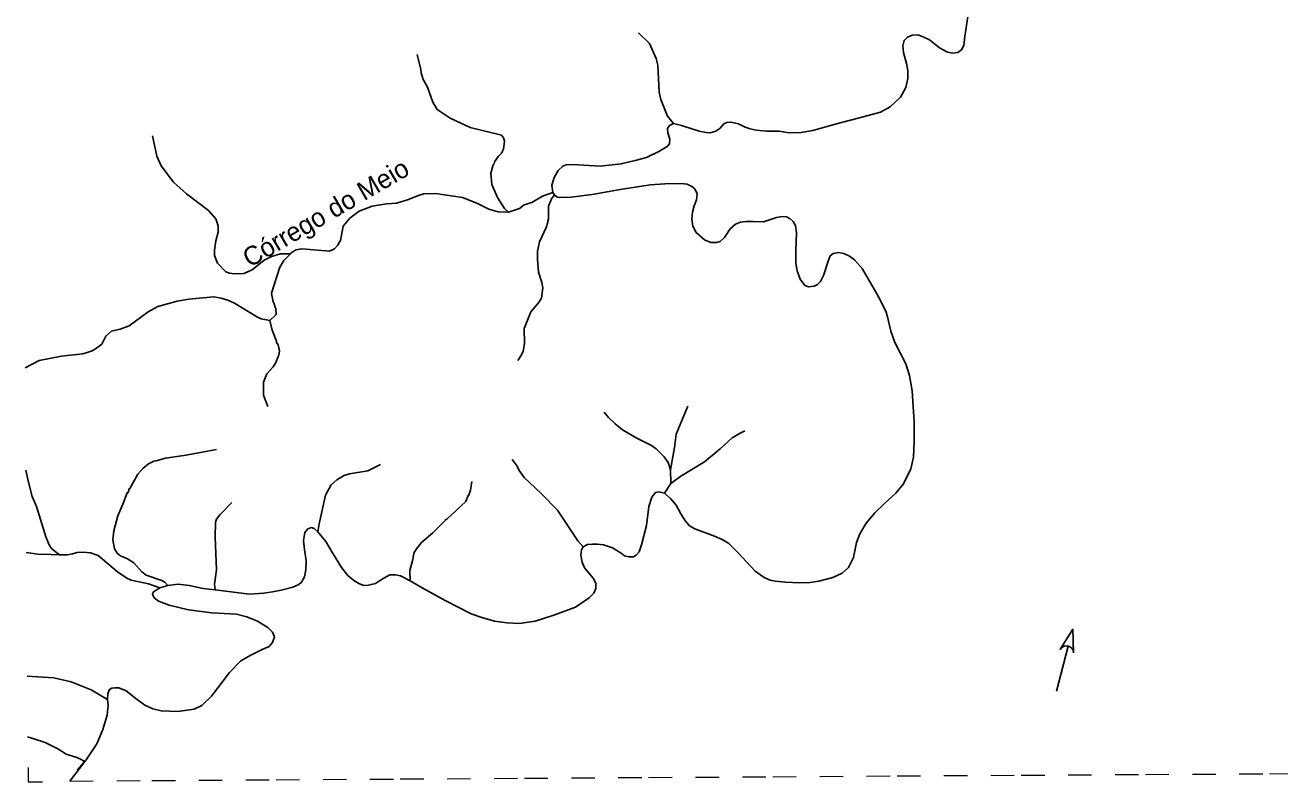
# Model space of a CAD drawing. Extents: x 396 to 422.2, y 7649.8 to 7677.6.
# Drawn here: x 396.23 to 401.58, y 7649.82 to 7653.05 of the extents above; entities that cross this region are included whole.
import ezdxf
from ezdxf.enums import TextEntityAlignment as Align

# ---------------------------------------------------------------- set-up
doc = ezdxf.new("R2010")
doc.units = 0
doc.header["$LTSCALE"] = 0.032
doc.linetypes.add('SHORT_DASHED', pattern=[2.7, 1.5, -1.2])
for name, color, linetype, lineweight in [('10', 7, 'Continuous', 25), ('2', 7, 'Continuous', 25), ('62', 7, 'SHORT_DASHED', 13), ('63', 7, 'Continuous', 13), ('7', 7, 'Continuous', 25)]:
    doc.layers.add(name, color=color, linetype=linetype, lineweight=lineweight)
doc.layers.add('61', color=7, linetype='Continuous')

msp = doc.modelspace()

# ---------------------------------------------------------------- linework, layer by layer
at = {"layer": '10'}
msp.add_line((400.6229, 7650.2102), (400.6732, 7650.4021), dxfattribs=at)
msp.add_lwpolyline([(400.6957, 7650.3734), (400.6941, 7650.3817), (400.6921, 7650.3873), (400.6862, 7650.3949), (400.6767, 7650.401), (400.6732, 7650.4021), (400.6649, 7650.403), (400.6575, 7650.4018), (400.6504, 7650.3995), (400.6446, 7650.3949), (400.639, 7650.3881), (400.6922, 7650.4744)], close=True, dxfattribs=at)
at = {"layer": '2'}
msp.add_line((396.4167, 7649.8267), (396.4802, 7649.9108), dxfattribs=at)
for points in [[(398.9898, 7652.632), (399.0237, 7652.6237), (399.0999, 7652.5996), (399.1289, 7652.5936), (399.1469, 7652.5926), (399.171, 7652.5986), (399.188, 7652.6107), (399.204, 7652.6297), (399.217, 7652.6367), (399.2351, 7652.6377), (399.2671, 7652.6307), (399.2962, 7652.6167), (399.3172, 7652.6086), (399.3432, 7652.6036), (399.3863, 7652.5996), (399.4404, 7652.5986), (399.4825, 7652.5926), (399.5345, 7652.5936), (399.5846, 7652.6016), (399.6848, 7652.6307), (399.7989, 7652.6607), (399.8731, 7652.6808), (399.9141, 7652.7028), (399.9572, 7652.7439), (399.9812, 7652.7859), (399.9892, 7652.824), (399.9892, 7652.857), (399.9832, 7652.8871), (399.9712, 7652.9352), (399.9682, 7652.9632), (399.9732, 7652.9862), (399.9882, 7653.0003), (400.0073, 7653.0083), (400.0313, 7653.0093), (400.0543, 7653.0013), (400.0814, 7652.9882), (400.1244, 7652.9542), (400.1585, 7652.9362), (400.1805, 7652.9321), (400.2026, 7652.9342), (400.2176, 7652.9462), (400.2276, 7652.9642), (400.2326, 7653.0033), (400.2486, 7653.1164)], [(398.4754, 7652.3369), (398.4719, 7652.3683), (398.4809, 7652.4013), (398.4979, 7652.4314), (398.518, 7652.4504), (398.532, 7652.4554), (398.561, 7652.4564), (398.6081, 7652.4544), (398.6772, 7652.4504), (398.7673, 7652.4594), (398.8264, 7652.4744), (398.8745, 7652.4865), (398.9306, 7652.5135), (398.9636, 7652.5335), (398.9737, 7652.5456), (398.9747, 7652.5656), (398.9657, 7652.5916), (398.9646, 7652.6107), (398.9727, 7652.6227), (398.9898, 7652.632)], [(398.9522, 7651.0542), (398.9787, 7651.0312), (399.0017, 7651.0042), (399.0217, 7650.9661), (399.0408, 7650.9351), (399.0588, 7650.916), (399.0808, 7650.902), (399.165, 7650.872), (399.198, 7650.8569), (399.2261, 7650.8399), (399.2661, 7650.7998), (399.3382, 7650.7227), (399.3763, 7650.6957), (399.4023, 7650.6837), (399.4254, 7650.6787), (399.4674, 7650.6747), (399.5275, 7650.6716), (399.5726, 7650.6737), (399.6096, 7650.6787), (399.6687, 7650.6947), (399.7088, 7650.7137), (399.7368, 7650.7377), (399.7569, 7650.7798), (399.7699, 7650.8439), (399.7849, 7650.882), (399.812, 7650.927), (399.849, 7650.9711), (399.8891, 7651.0112), (399.9382, 7651.0542), (399.9712, 7651.0943), (400.0013, 7651.1584), (400.0133, 7651.2085), (400.0163, 7651.2776), (400.0163, 7651.3597), (400.0073, 7651.4909), (399.9962, 7651.557), (399.9802, 7651.6071), (399.9342, 7651.6972), (399.9171, 7651.7453), (399.9031, 7651.8064), (399.8961, 7651.8274), (399.8751, 7651.8715), (399.856, 7651.9076), (399.82, 7651.9697), (399.7939, 7652.0137), (399.7619, 7652.0498), (399.7409, 7652.0658), (399.7158, 7652.0768), (399.6938, 7652.0808), (399.6707, 7652.0778), (399.6587, 7652.0668), (399.6497, 7652.0438), (399.6297, 7651.9827), (399.6167, 7651.9576), (399.6036, 7651.9446), (399.5896, 7651.9376), (399.5656, 7651.9346), (399.5496, 7651.9406), (399.5305, 7651.9677), (399.5175, 7652.0027), (399.5115, 7652.0358), (399.5115, 7652.0878), (399.5145, 7652.165), (399.5105, 7652.196), (399.5005, 7652.213), (399.4875, 7652.2251), (399.4724, 7652.2341), (399.4534, 7652.2351), (399.4294, 7652.2311), (399.4043, 7652.222), (399.3743, 7652.212), (399.3282, 7652.213), (399.2982, 7652.214), (399.2761, 7652.211), (399.2541, 7652.203), (399.2321, 7652.183), (399.207, 7652.1459), (399.189, 7652.1289), (399.173, 7652.1239), (399.1499, 7652.1239), (399.1229, 7652.1359), (399.0868, 7652.167), (399.0728, 7652.194), (399.0678, 7652.2251), (399.0708, 7652.2531), (399.0788, 7652.2811), (399.0878, 7652.3062), (399.0908, 7652.3312), (399.0808, 7652.3533), (399.0688, 7652.3623), (399.0488, 7652.3723), (399.0227, 7652.3763), (398.9536, 7652.3743), (398.8925, 7652.3703), (398.7714, 7652.3512)], [(398.7714, 7652.3512), (398.6432, 7652.3282), (398.554, 7652.3172), (398.5039, 7652.3162), (398.4939, 7652.3182), (398.4826, 7652.3274), (398.4754, 7652.3369)], [(398.6048, 7650.8262), (398.6231, 7650.8359), (398.6442, 7650.8369), (398.6662, 7650.8369), (398.6912, 7650.8349), (398.7303, 7650.8209), (398.7663, 7650.7988), (398.7814, 7650.7878), (398.7994, 7650.7828), (398.8194, 7650.7828), (398.8314, 7650.7898), (398.8435, 7650.8049), (398.8535, 7650.8349), (398.8745, 7650.917), (398.8855, 7650.9982), (398.8975, 7651.0382), (398.9136, 7651.0572), (398.9246, 7651.0602), (398.9396, 7651.0582), (398.9522, 7651.0542)], [(397.0362, 7650.642), (397.1819, 7650.6236), (397.244, 7650.6276), (397.281, 7650.6346), (397.3181, 7650.6416), (397.3672, 7650.6536), (397.3932, 7650.6656), (397.4042, 7650.6757), (397.4173, 7650.6977), (397.4233, 7650.7277), (397.4243, 7650.7658), (397.4173, 7650.8149), (397.4122, 7650.8529), (397.4183, 7650.887), (397.4313, 7650.902), (397.4463, 7650.908), (397.4583, 7650.904), (397.4742, 7650.8893)], [(397.4742, 7650.8893), (397.5074, 7650.8489), (397.5364, 7650.7998), (397.5745, 7650.7377), (397.6015, 7650.7037), (397.6276, 7650.6817), (397.6516, 7650.6676), (397.6706, 7650.6616), (397.6897, 7650.6626), (397.7197, 7650.6696), (397.7372, 7650.6807), (397.7548, 7650.6917), (397.7808, 7650.7057), (397.8049, 7650.7067), (397.8269, 7650.7017), (397.867, 7650.6815)], [(397.867, 7650.6815), (397.918, 7650.6516), (398.0162, 7650.5965), (398.1274, 7650.5404), (398.1734, 7650.5244), (398.2265, 7650.5094), (398.2796, 7650.5014), (398.3337, 7650.4984), (398.3998, 7650.5094), (398.4799, 7650.5344), (398.573, 7650.5685), (398.6301, 7650.6085), (398.6502, 7650.6276), (398.6592, 7650.6486), (398.6592, 7650.6706), (398.6472, 7650.6927), (398.6111, 7650.7357), (398.6001, 7650.7598), (398.5951, 7650.7908), (398.5981, 7650.8129), (398.6048, 7650.8262)], [(396.8346, 7650.6612), (396.8784, 7650.6666), (396.9255, 7650.6616), (396.9856, 7650.6486), (397.0362, 7650.642)], [(396.5771, 7650.1748), (396.579, 7650.1999), (396.586, 7650.2179), (396.595, 7650.223), (396.609, 7650.225), (396.626, 7650.224), (396.6571, 7650.2119), (396.6981, 7650.1789), (396.7362, 7650.1498), (396.7703, 7650.1348), (396.8063, 7650.1258), (396.8764, 7650.1238), (396.9465, 7650.1328), (396.9796, 7650.1488), (397.0206, 7650.1889), (397.0978, 7650.2901), (397.1458, 7650.3391), (397.1889, 7650.3632), (397.236, 7650.3872), (397.266, 7650.4002), (397.281, 7650.4173), (397.2891, 7650.4413), (397.281, 7650.4613), (397.261, 7650.4814), (397.2169, 7650.5094), (397.1709, 7650.5274), (397.1268, 7650.5384), (397.0226, 7650.5445), (396.9225, 7650.5575), (396.8394, 7650.5765), (396.7953, 7650.5945), (396.7763, 7650.6085), (396.7692, 7650.6246), (396.7733, 7650.6346), (396.8005, 7650.6505), (396.8346, 7650.6612)], [(396.4802, 7649.9108), (396.4498, 7649.8744), (396.4858, 7649.9175), (396.5319, 7649.9856), (396.5579, 7650.0467), (396.5759, 7650.1078), (396.58, 7650.1508), (396.5771, 7650.1748)]]:
    msp.add_lwpolyline(points, dxfattribs=at)
at = {"layer": '62'}
msp.add_lwpolyline([(396.4167, 7649.8267), (396.7664, 7649.8289), (397.2959, 7649.8322), (397.8253, 7649.8355), (398.3548, 7649.8388), (398.8842, 7649.842), (399.4136, 7649.8453), (399.9431, 7649.8485), (400.4725, 7649.8518), (401.002, 7649.855), (401.5314, 7649.8581), (402.0608, 7649.8613), (402.5903, 7649.8645), (403.1197, 7649.8676), (403.6491, 7649.8707), (404.1702, 7649.8738)], dxfattribs=at)
at = {"layer": '63'}
msp.add_lwpolyline([(396.2389, 7649.8846), (396.2389, 7649.823), (396.2996, 7649.823)], dxfattribs=at)
at = {"layer": '7'}
msp.add_line((398.9782, 7651.0964), (398.9522, 7651.0542), dxfattribs=at)
for points in [[(398.8411, 7653.0181), (398.8882, 7652.9732), (398.9168, 7652.9088), (398.9232, 7652.8801), (398.9296, 7652.7649), (398.9356, 7652.7347), (398.9645, 7652.6625), (398.9898, 7652.632)], [(397.8977, 7652.9256), (397.9135, 7652.8625), (397.9145, 7652.8475), (397.9231, 7652.8201), (397.941, 7652.7868), (397.9637, 7652.7223), (397.9831, 7652.6919), (398.0375, 7652.655), (398.123, 7652.615), (398.2564, 7652.5817), (398.2659, 7652.5705), (398.2693, 7652.556), (398.266, 7652.5216), (398.2564, 7652.5045), (398.2444, 7652.4929), (398.2274, 7652.4688), (398.2257, 7652.4604), (398.2213, 7652.456), (398.2119, 7652.4194), (398.2153, 7652.3721), (398.2393, 7652.3161), (398.2702, 7652.2689), (398.287, 7652.254)], [(396.7684, 7652.5795), (396.7877, 7652.4922), (396.8063, 7652.4517), (396.8583, 7652.382), (396.9145, 7652.3319), (397.0071, 7652.261), (397.0392, 7652.2247), (397.049, 7652.1949), (397.0491, 7652.168), (397.0396, 7652.1308), (397.0339, 7652.0918), (397.0338, 7652.0686), (397.0459, 7652.0356), (397.0811, 7651.9991), (397.0973, 7651.9932), (397.1189, 7651.9901), (397.1579, 7651.9925), (397.1933, 7652.0073), (397.2455, 7652.0481), (397.2769, 7652.0649), (397.3151, 7652.0754), (397.3567, 7652.0763)], [(397.3567, 7652.0763), (397.3592, 7652.0789), (397.3801, 7652.0927), (397.4053, 7652.0978), (397.5241, 7652.0866), (397.5448, 7652.0976), (397.5583, 7652.1116), (397.5705, 7652.1322), (397.5822, 7652.1938), (397.6109, 7652.2277), (397.6497, 7652.2572), (397.7051, 7652.2784), (397.7668, 7652.2891), (397.8093, 7652.2925), (397.8558, 7652.3057), (397.9029, 7652.3249), (397.9256, 7652.3313), (397.9762, 7652.333), (398.0902, 7652.3159), (398.1522, 7652.2926), (398.2034, 7652.2667), (398.2425, 7652.2548), (398.2847, 7652.2532), (398.287, 7652.254)], [(398.287, 7652.254), (398.3341, 7652.2696), (398.3533, 7652.285), (398.3866, 7652.2945), (398.4322, 7652.322), (398.4754, 7652.3369)], [(398.4826, 7652.3274), (398.4704, 7652.3107), (398.4575, 7652.2787), (398.4574, 7652.2218), (398.4543, 7652.2186), (398.4542, 7652.2102), (398.447, 7652.1875), (398.4182, 7652.1271), (398.4105, 7652.0877), (398.4097, 7652.0527), (398.4145, 7651.9977), (398.4295, 7651.9531), (398.4335, 7651.931), (398.427, 7651.8862), (398.4151, 7651.8666), (398.3819, 7651.828), (398.3539, 7651.7569), (398.3546, 7651.6934), (398.3492, 7651.6606), (398.3422, 7651.6449), (398.326, 7651.6209)], [(397.2697, 7651.7911), (397.2963, 7651.8167), (397.2948, 7651.8434), (397.2915, 7651.8469), (397.2867, 7651.8669), (397.2833, 7651.869), (397.2764, 7651.9084), (397.3121, 7652.0185), (397.3293, 7652.0478), (397.3567, 7652.0763)], [(396.2259, 7651.5891), (396.2863, 7651.6209), (396.3805, 7651.6399), (396.4725, 7651.6488), (396.4905, 7651.6547), (396.5124, 7651.662), (396.531, 7651.6729), (396.5531, 7651.6907), (396.5701, 7651.724), (396.5946, 7651.7452), (396.6309, 7651.7547), (396.6692, 7651.769), (396.7501, 7651.8286), (396.7919, 7651.8517), (396.8749, 7651.8744), (396.9236, 7651.8825), (397.0309, 7651.8927), (397.0615, 7651.8873), (397.0898, 7651.8787), (397.1189, 7651.8658), (397.2162, 7651.8052), (397.232, 7651.7984), (397.2697, 7651.7911)], [(397.2697, 7651.7911), (397.279, 7651.7501), (397.2979, 7651.7034), (397.298, 7651.6978), (397.3043, 7651.6875), (397.3099, 7651.6615), (397.3072, 7651.6432), (397.3048, 7651.6372), (397.2949, 7651.6123), (397.283, 7651.5939), (397.2571, 7651.5639), (397.2421, 7651.5283), (397.2421, 7651.4731), (397.2605, 7651.4247)], [(399.0517, 7651.4263), (399.0016, 7651.3066), (398.9949, 7651.2496), (398.9773, 7651.1541)], [(398.6944, 7651.4), (398.7124, 7651.3779), (398.741, 7651.3499), (398.7731, 7651.3252), (398.8343, 7651.2895), (398.8961, 7651.2579), (398.9168, 7651.2436), (398.9501, 7651.2095), (398.9674, 7651.1852), (398.9773, 7651.1541)], [(399.2941, 7651.3203), (399.2709, 7651.3098), (399.2406, 7651.2906), (399.1893, 7651.2434), (399.1221, 7651.1889), (399.0213, 7651.1278), (398.9782, 7651.0964)], [(397.042, 7651.2405), (396.9195, 7651.218), (396.903, 7651.215), (396.8251, 7651.2044), (396.7842, 7651.1934), (396.7744, 7651.1908), (396.752, 7651.1798), (396.7278, 7651.16), (396.7064, 7651.1354), (396.6726, 7651.0741), (396.669, 7651.0728), (396.6648, 7651.0582), (396.6615, 7651.0565), (396.643, 7651.0072), (396.6206, 7650.958), (396.6042, 7650.8947), (396.6001, 7650.856), (396.6066, 7650.8174), (396.6187, 7650.7991), (396.6327, 7650.7879), (396.6631, 7650.7746), (396.6889, 7650.7577), (396.723, 7650.7196), (396.7425, 7650.7049), (396.8092, 7650.6824), (396.8213, 7650.6748), (396.8346, 7650.6612)], [(396.2286, 7651.1536), (396.2397, 7651.1073), (396.2558, 7651.0403), (396.2742, 7650.9973), (396.3139, 7650.869), (396.3265, 7650.8366), (396.337, 7650.8203), (396.3537, 7650.8058), (396.3721, 7650.7911)], [(397.7406, 7651.1767), (397.6865, 7651.1501), (397.6093, 7651.1368), (397.5863, 7651.1302), (397.5542, 7651.1118), (397.5312, 7651.091), (397.507, 7651.0461), (397.479, 7650.9233), (397.4742, 7650.8893)], [(398.3028, 7651.1982), (398.3235, 7651.1702), (398.3318, 7651.1509), (398.3528, 7651.1211), (398.4246, 7651.0547), (398.4952, 7650.9817), (398.5826, 7650.8515), (398.6048, 7650.8262)], [(398.9773, 7651.1541), (398.9789, 7651.0975), (398.9782, 7651.0964)], [(398.1306, 7651.1041), (398.1247, 7651.0674), (398.1178, 7651.0462), (398.1147, 7651.0449), (398.1044, 7651.0198), (398.0234, 7650.9438), (398.0176, 7650.9414), (398.0181, 7650.9391), (397.9644, 7650.8861), (397.9153, 7650.8442), (397.8938, 7650.818), (397.8834, 7650.7991), (397.8793, 7650.7714), (397.8667, 7650.7255), (397.867, 7650.6815)], [(397.1074, 7651.0148), (397.0557, 7650.9624), (397.0415, 7650.944), (397.038, 7650.9306), (397.0356, 7650.8666), (397.0412, 7650.7283), (397.0332, 7650.6669), (397.0362, 7650.642)], [(396.2308, 7650.8018), (396.2795, 7650.7948), (396.3373, 7650.7927), (396.3721, 7650.7911)], [(396.3721, 7650.7911), (396.3897, 7650.7911), (396.406, 7650.7911), (396.4286, 7650.7955), (396.4478, 7650.801), (396.4729, 7650.8027), (396.5049, 7650.8003), (396.5371, 7650.789), (396.6203, 7650.7194), (396.6597, 7650.6926), (396.6782, 7650.6835), (396.7515, 7650.6685), (396.8005, 7650.6505)], [(396.2341, 7650.2736), (396.257, 7650.2723), (396.349, 7650.267), (396.423, 7650.2505), (396.5081, 7650.2158), (396.5771, 7650.1748)], [(396.2358, 7650.0156), (396.2503, 7650.0109), (396.312, 7649.9909), (396.3661, 7649.9638), (396.4011, 7649.9412), (396.4467, 7649.927), (396.4588, 7649.9212), (396.4802, 7649.9108)]]:
    msp.add_lwpolyline(points, dxfattribs=at)

# ---------------------------------------------------------------- texts
at = {"layer": '61'}
msp.add_text('Córrego do Meio', height=0.08, rotation=30.289, dxfattribs=at).set_placement((397.5275, 7652.2162), align=Align.CENTER)

doc.saveas('drawing.dxf')
